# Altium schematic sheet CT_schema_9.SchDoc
size 274 x 160 mm
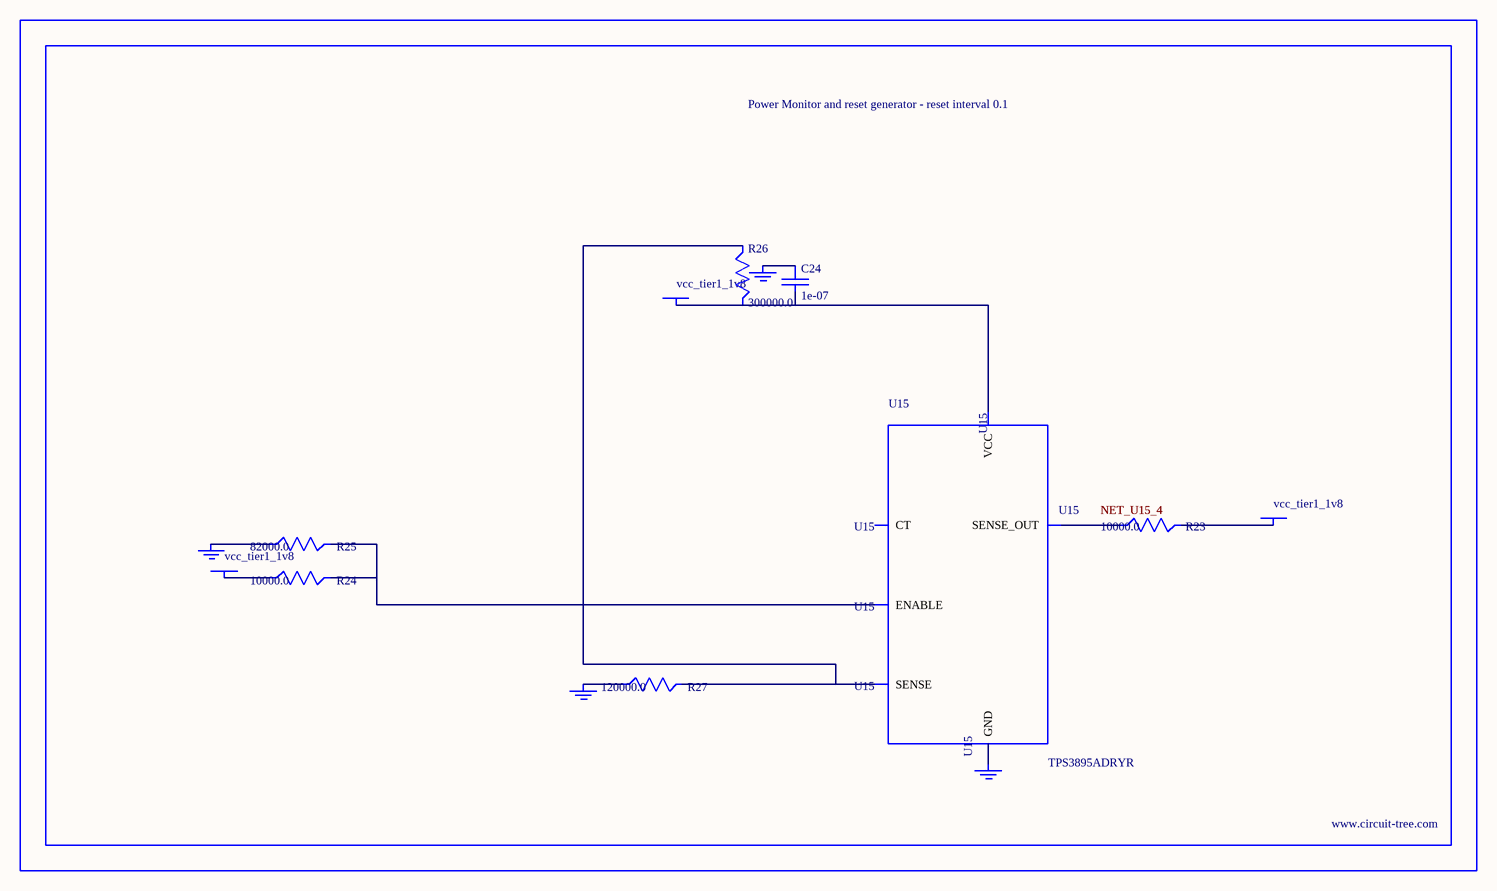
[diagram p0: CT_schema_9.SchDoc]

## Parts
BORDER8  (no value)
C24  1e-07  [C0402]
GND_INSTANCE_8_0  (no value)
GND_INSTANCE_8_1  (no value)
GND_INSTANCE_8_2  (no value)
GND_INSTANCE_8_3  (no value)
POWER_INSTANCE_8_0  vcc_tier1_1v8
POWER_INSTANCE_8_1  vcc_tier1_1v8
POWER_INSTANCE_8_2  vcc_tier1_1v8
R23  10000.0  [R0603]
R24  10000.0  [R0603]
R25  82000.0  [R0603]
R26  300000.0  [R0603]
R27  120000.0  [R0603]
U15  TPS3895ADRYR  [SON-6]

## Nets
NetC24_1: C24.1 GND_INSTANCE_8_2.0(GND)
NetC24_2: C24.2 POWER_INSTANCE_8_2.0(PWR) R26.2 U15.6(VCC)
NetGND_INSTANCE_8_0_0: GND_INSTANCE_8_0.0(GND) R25.1
NetGND_INSTANCE_8_1_0: GND_INSTANCE_8_1.0(GND) R27.1
NetGND_INSTANCE_8_3_0: GND_INSTANCE_8_3.0(GND) U15.2(GND)
NetPOWER_INSTANCE_8_0_0: POWER_INSTANCE_8_0.0(PWR) R24.1
NetPOWER_INSTANCE_8_1_0: POWER_INSTANCE_8_1.0(PWR) R23.2
NetR23_1: R23.1 U15.4(SENSE_OUT)
NetR24_2: R24.2 R25.2 U15.1(ENABLE)
NetR26_1: R26.1 R27.2 U15.3(SENSE)

Not connected (* = marked no-connect by the designer): U15 5(CT)

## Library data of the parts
BORDER8 = BORDER_PAGE8
C24 = C0402C104K3RACTU
GND_INSTANCE_8_0-GND_INSTANCE_8_3 = GND
POWER_INSTANCE_8_0-POWER_INSTANCE_8_2 = PWR
R23 R24 = RC0603JR-0710KL
R25 = RC0603JR-0782KL
R26 = RC0603JR-07300KL
R27 = RC0603JR-07120KL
